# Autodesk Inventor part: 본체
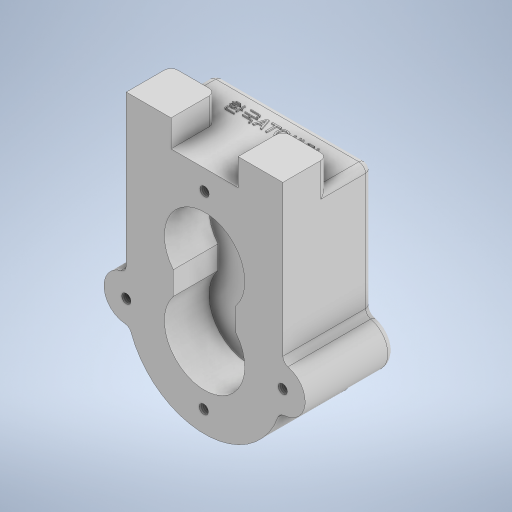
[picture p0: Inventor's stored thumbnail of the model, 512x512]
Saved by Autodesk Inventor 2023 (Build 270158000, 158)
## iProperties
Created: 2024-03
Part Number: 본체
Material: 일반
Document SubType Name: Modeling
Designer: asung
Density: 1 g/cm^3
Appearance: 기본값
Author: asung
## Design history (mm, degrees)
sketch "스케치1"
  geometry: L1 (-35, 0)-(35, 0); L2 (35, 0)-(35, 68); L3 (35, 68)-(-35, 68); L4 (-35, 68)-(-35, 0); C1 r 10 at (-35, 0); C2 r 10 at (35, 0); A1 r 35 centre (0, 0) between (-35, 0) and (35, 0); 7 further points
  constraints: 8 end point, 3 centre point, 2 horizontal alignment, 2 midpoint, 2 parallel, 2 point on circle, 1 coincident, 1 horizontal, 1 perpendicular, 1 vertical alignment
  dimensions: "d1" = 70 diameter of A1; "d4" = 10 radius of C1; "d5" = 10 radius of C2; "d6" = 70 distance of L3.end L2.end; "d7" = 68 distance of L2.end L1.end
extrude "돌출1" new body sketch "스케치1" distance "d8" = 40; taper "d9" = 0 deg
sketch "스케치2"
  geometry: L1 (0, 0)-(0, 33); L2 (-14, 0)-(0, 0); L3 (14, 11.314)-(14, 21.686); L4 (-14, 21.686)-(-14, 11.314); A1 r 18 centre (0, 33) between (14, 21.686) and (-14, 21.686); A2 r 18 centre (0, 0) between (-14, 11.314) and (14, 11.314); 1 further point
  constraints: 8 end point, 4 point on circle, 2 centre point, 2 coincident, 2 vertical, 1 horizontal
  dimensions: "d11" = 33 distance of L1.start L1.end
extrude "돌출2" cut sketch "스케치2" distance "d19" = 20; taper "d20" = 0 deg
sketch "스케치3"
  geometry: A1 r 18 centre (0, 33) between (14, 21.686) and (-14, 21.686) reference; 2 further points
  constraints: 1 coincident
hole "구멍1" sketch "스케치3" at (0, 33) diameter "d21" = 15; stored, may be unused: countersink angle "d25" = 90 deg, drill point angle "d27" = 0 deg; dims "d22" = 8, "d23" = 20, "d24" = 10, "d26" = 30
sketch "스케치5"
  geometry: L1 (35, 68)-(35, 10) reference; L2 (-35, 68)-(35, 68) reference; L3 (-35, 10)-(-35, 68) reference; C1 r 7.5 at (0, 33) reference; C2 r 7.5 at (0, 33) reference; C3 r 26 at (0, 33); A1 r 10 centre (-35, 0) between (-35, 10) and (-33.571, -9.897) reference; A2 r 35 centre (0, 0) between (-33.571, -9.897) and (33.571, -9.897) reference; A3 r 10 centre (35, 0) between (33.571, -9.897) and (35, 10) reference; 1 further point
  constraints: 1 centre point, 1 coincident
  dimensions: "d35" = 52 diameter of C3
extrude "돌출3" join sketch "스케치5" distance "d36" = 6; taper "d37" = 0 deg
sketch "스케치6" dims "d38" = 42
  geometry: 3 further points
  constraints: 1 horizontal alignment, 2 other
hole "구멍3" sketch "스케치6" at (21, 0) diameter "d39" = 3.242; stored, may be unused: countersink angle "d43" = 90 deg, drill point angle "d45" = 118 deg; dims "d40" = 8, "d41" = 25, "d42" = 7.3, "d44" = 10
sketch "스케치7"
  geometry: C1 r 26 at (0, 0) reference; 2 further points
  constraints: 1 coincident
hole "구멍4" sketch "스케치7" at (0, 0) diameter "d49" = 15; stored, may be unused: countersink angle "d53" = 90 deg, drill point angle "d55" = 0 deg; dims "d50" = 8, "d51" = 25, "d52" = 7.3, "d54" = 50
fillet "모깎기1" dims "d56" = 3
chamfer "모따기1" distance "d57" = 1; stored, may be unused: second distance "d58" = 2, angle "d59" = 45 deg
sketch "스케치8"
  geometry: L1 (35, 68)-(35, 10) reference; L2 (-35, 68)-(35, 68) reference; L3 (-35, 10)-(-35, 68) reference; C1 r 29 at (0, 33) reference; A1 r 10 centre (-35, 0) between (-35, 10) and (-33.571, -9.897) reference; A2 r 35 centre (0, 0) between (-33.571, -9.897) and (33.571, -9.897) reference; A3 r 10 centre (35, 0) between (33.571, -9.897) and (35, 10) reference; 1 further point
  node "투영된 루프2"
sketch "스케치11"
  geometry: A1 r 10 centre (-35, 0) between (-35, 10) and (-33.571, -9.897) reference; 2 further points
  constraints: 1 coincident
hole "구멍6" sketch "스케치11" at (-35, 0) diameter "d69" = 4.134; stored, may be unused: countersink angle "d73" = 90 deg, drill point angle "d75" = 120 deg; dims "d70" = 10, "d71" = 4, "d72" = 2, "d74" = 12
sketch "스케치12"
  geometry: A1 r 10 centre (35, 0) between (33.571, -9.897) and (35, 10) reference; 2 further points
  constraints: 1 coincident
hole "구멍7" sketch "스케치12" at (35, 0) diameter "d76" = 4.134; stored, may be unused: countersink angle "d80" = 90 deg, drill point angle "d82" = 120 deg; dims "d77" = 10, "d78" = 4, "d79" = 2, "d81" = 12
sketch "스케치13"
  geometry: 2 further points
hole "구멍8" sketch "스케치13" at (1.299, -1.231) diameter "d83" = 10; stored, may be unused: countersink angle "d87" = 90 deg, drill point angle "d89" = 120 deg; dims "d84" = 10, "d85" = 4, "d86" = 2, "d88" = 12
sketch "스케치14"
  geometry: C1 r 2.067 at (-35, 0) reference; C2 r 10 at (-35, 0); C3 r 2.067 at (35, 0) reference; C4 r 10 at (35, 0); 1 further point
  constraints: 2 centre point, 2 coincident
  dimensions: "d90" = 20 diameter of C2; "d91" = 20 diameter of C4
sketch "스케치15"
  geometry: 1 further point
node "작업 평면3"
sketch "스케치16"
  geometry: L1 (0, -20)-(20, -20); L2 (20, -20)-(20, -40); L3 (20, -40)-(0, -40); L4 (0, -40)-(0, -20); L5 (50, -20)-(70, -20); L6 (70, -20)-(70, -40); L7 (70, -40)-(50, -40); L8 (50, -40)-(50, -20); L9 (70, 0)-(0, 0) reference; L10 (0, 0)-(0, -40) reference; L11 (70, -40)-(0, -40) reference; L12 (70, 0)-(70, -40) reference; 1 further point
  constraints: 16 end point, 4 parallel, 2 horizontal, 2 perpendicular, 2 point on line
  dimensions: "d93" = 20 distance of L3.end L2.end; "d94" = 20 distance of L6.end L7.end; "d95" = 30 distance of L7.end L2.end; "d96" = 20 distance of L2.end L1.end
extrude "돌출4" join sketch "스케치16" stored distance "d97" = 12; taper "d98" = 0 deg
fillet "모깎기2" dims "d99" = 3
sketch "스케치17"
  geometry: L1 (17, -20)-(3, -20) reference; L2 (0, -23)-(0, -40) reference; L3 (0, -40)-(20, -40) reference; L4 (20, -40)-(20, -23) reference; L5 (67, -20)-(53, -20) reference; L6 (50, -23)-(50, -40) reference; L7 (50, -40)-(70, -40) reference; L8 (70, -40)-(70, -23) reference; A1 r 3 centre (17, -23) between (20, -23) and (17, -20) reference; A2 r 3 centre (3, -23) between (3, -20) and (0, -23) reference; A3 r 3 centre (67, -23) between (70, -23) and (67, -20) reference; A4 r 3 centre (53, -23) between (53, -20) and (50, -23) reference; 1 further point
  node "투영된 루프4"
  node "투영된 루프5"
sketch "스케치18"
  geometry: 1 further point
sketch "스케치19"
  geometry: L1 (30, 0)-(0, 0) reference; L2 (47, 40)-(-17, 40) reference; 3 further points
  constraints: 1 midpoint, 1 vertical alignment, 1 other
  dimensions: "d100" = 30 distance from line of L1 point (15, 30)
feature "엠보싱1" sketch "스케치19" dims "d1" = 70, "d4" = 10, "d5" = 10, "d6" = 70, "d7" = 68, "d101" = 0.5, "d102" = 0
sketch "스케치20"
  geometry: L1 (35, 10)-(35, 80) reference; L2 (15, 80)-(35, 80) reference; L3 (15, 80)-(15, 68) reference; L4 (15, 68)-(-15, 68) reference; L5 (-15, 80)-(-15, 68) reference; L6 (-35, 80)-(-15, 80) reference; L7 (-35, 80)-(-35, 10) reference; L8 (-14, 11.314)-(-14, 21.686) reference; L9 (14, 21.686)-(14, 11.314) reference; L10 (0, 33)-(0, 59); C1 r 2.067 at (35, 0) reference; C2 r 2.067 at (-35, 0) reference; C3 r 10 at (0, 33) reference; A1 r 10 centre (-35, 0) between (-35, 10) and (-33.571, -9.897) reference; A2 r 35 centre (0, 0) between (-33.571, -9.897) and (33.571, -9.897) reference; A3 r 10 centre (35, 0) between (33.571, -9.897) and (35, 10) reference; A4 r 18 centre (0, 0) between (-14, 11.314) and (14, 11.314) reference; A5 r 18 centre (0, 33) between (14, 21.686) and (-14, 21.686) reference; 2 further points
  constraints: 2 end point, 1 coincident, 1 vertical
  dimensions: "d103" = 26 distance of L10.start L10.end
hole "구멍9" sketch "스케치20" at (0, 59) diameter "d104" = 4.134; stored, may be unused: countersink angle "d108" = 90 deg, drill point angle "d110" = 120 deg; dims "d105" = 10, "d106" = 4, "d107" = 2, "d109" = 12
sketch "스케치21"
  geometry: L1 (-0.336, 68)-(-0.336, 68.5) reference; L2 (-0.336, 68.5)-(-0.336, -25.5); 2 further points
  constraints: 2 end point, 1 coincident, 1 vertical
  dimensions: "d111" = 94 distance of L1.end L2.end
hole "구멍10" sketch "스케치21" at (-0.336, -25.5) diameter "d112" = 4.134; stored, may be unused: countersink angle "d116" = 90 deg, drill point angle "d118" = 120 deg; dims "d113" = 10, "d114" = 4, "d115" = 2, "d117" = 12
fillet "모깎기3" dims "d119" = 3
sketch "스케치22"
  geometry: 1 further point
fillet "모깎기4" dims "d120" = 3
feature "Ӧ耀Ө耀Ӫ耀Ӭ耀Ӯ耀Ӱ耀Ӳ耀Ӵ耀" dims "d1" = 70, "d4" = 10, "d5" = 10, "d6" = 70, "d7" = 68, "d8" = 40, "d9" = 0, "d10" = 36, "d11" = 33, "d12" = 36, "d19" = 20, "d20" = 0, "d21" = 15, "d22" = 8, "d23" = 20, "d24" = 10, "d25" = 90 deg, "d26" = 30, "d27" = 0, "d35" = 52, "d36" = 6, "d37" = 0, "d38" = 42, "d39" = 3.242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
node "솔리드1"
pattern_circular "원형 패턴1" dims angle "d47" = 360 deg
node "투영된 루프1"
node "투영된 루프3"
node "투영된 루프6"
feature "A9D066F2-1C7D-4E18-AEED-F7BC21143FA4" dims "d21" = 15, "d22" = 8, "d23" = 20, "d24" = 10, "d25" = 90 deg, "d26" = 30, "d27" = 0
